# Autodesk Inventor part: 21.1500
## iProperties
Created: 2007-03
Part Number: 21.1500
Material: Steel, Mild
Description: M4x8 CSUNK
Document SubType Name: Modeling
Standard: DIN 7991
Designer: Andy Moles
Standards Organization: DIN
Language: en-US
Size Designation: M4x8
Categories: <MemberInstance Version="R10.0.0"><Categories><Category DisplayName="Fasteners" InternalName="e4da775c-781d-43d5-af7c-5136215cf5a6" Mnemonic="FSTN"><Category Di
Density: 7.86 g/cm^3
Mass: 1.06027 g
Surface Area: 2.08063 cm^2
Volume: 0.134894 cm^3
Author: Andy Moles
Revision Number: 1
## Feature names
1. Revolution1
2. Extrusion1
3. Fillet1
4. Chamfer1
